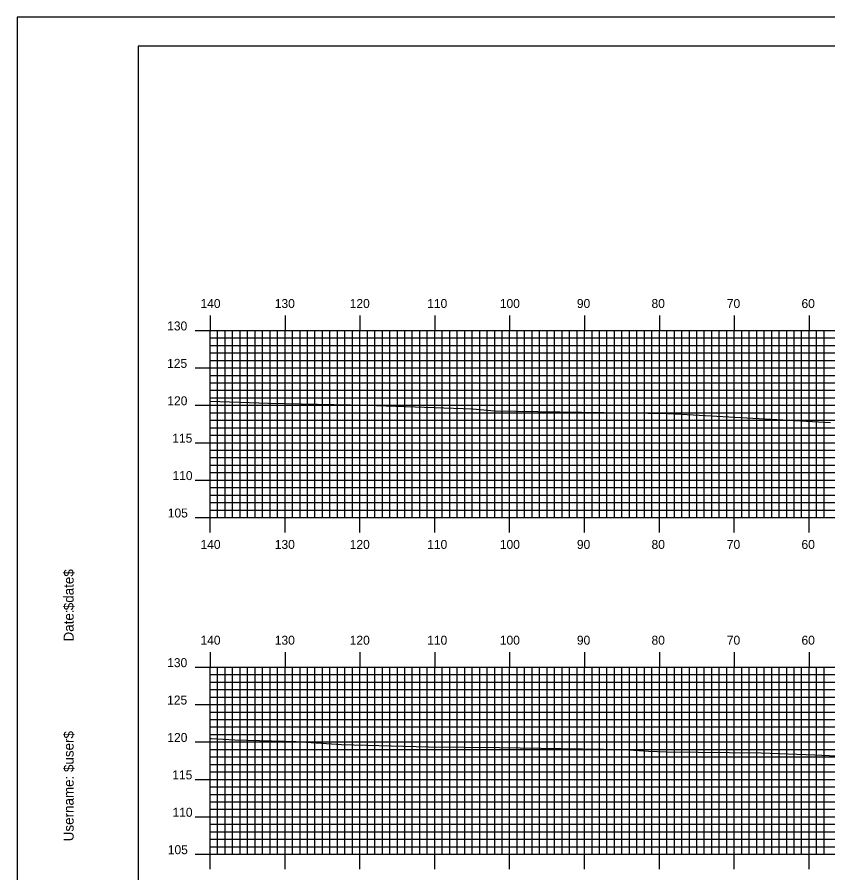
# Model space of a CAD drawing. Extents: x 1772022 to 1772366, y 442591 to 442811.
# Drawn here: x 1772022.3 to 1772130.6, y 442696.2 to 442810.5 of the extents above; entities that cross this region are included whole.
import ezdxf

# ---------------------------------------------------------------- set-up
doc = ezdxf.new("R2010")
doc.units = 0
for name, color, linetype in [('BORDER', 7, 'Continuous'), ('H_V ANNOTATION', 7, 'Continuous'), ('MAJOR', 7, 'Continuous'), ('MINOR', 7, 'Continuous'), ('PLOT BOUNDARY', 7, 'Continuous'), ('S_Roadway_Centerline', 7, 'Continuous')]:
    doc.layers.add(name, color=color, linetype=linetype)

msp = doc.modelspace()

# ---------------------------------------------------------------- linework, layer by layer
at = {"layer": 'BORDER'}
msp.add_lwpolyline([(1772038.49, 442596.67), (1772358.49, 442596.67), (1772358.49, 442806.67), (1772038.49, 442806.67)], close=True, dxfattribs=at)
at = {"layer": 'MAJOR'}
for p, q in [((1772048.09, 442770.67), (1772048.09, 442768.67)), ((1772058.09, 442770.67), (1772058.09, 442768.67)), ((1772068.09, 442770.67), (1772068.09, 442768.67)), ((1772078.09, 442770.67), (1772078.09, 442768.67)), ((1772088.09, 442770.67), (1772088.09, 442768.67)), ((1772098.09, 442770.67), (1772098.09, 442768.67)), ((1772108.09, 442770.67), (1772108.09, 442768.67)), ((1772118.09, 442770.67), (1772118.09, 442768.67)), ((1772128.09, 442770.67), (1772128.09, 442768.67)), ((1772046.09, 442768.67), (1772048.09, 442768.67)), ((1772048.09, 442768.67), (1772328.09, 442768.67)), ((1772048.09, 442743.67), (1772048.09, 442768.67)), ((1772048.09, 442743.67), (1772048.09, 442768.67)), ((1772048.09, 442768.67), (1772328.09, 442768.67)), ((1772058.09, 442743.67), (1772058.09, 442768.67)), ((1772068.09, 442743.67), (1772068.09, 442768.67)), ((1772078.09, 442743.67), (1772078.09, 442768.67)), ((1772088.09, 442743.67), (1772088.09, 442768.67)), ((1772098.09, 442743.67), (1772098.09, 442768.67)), ((1772108.09, 442743.67), (1772108.09, 442768.67)), ((1772118.09, 442743.67), (1772118.09, 442768.67)), ((1772128.09, 442743.67), (1772128.09, 442768.67)), ((1772046.09, 442763.67), (1772048.09, 442763.67)), ((1772048.09, 442763.67), (1772328.09, 442763.67)), ((1772046.09, 442758.67), (1772048.09, 442758.67)), ((1772048.09, 442758.67), (1772328.09, 442758.67)), ((1772046.09, 442753.67), (1772048.09, 442753.67)), ((1772048.09, 442753.67), (1772328.09, 442753.67)), ((1772046.09, 442748.67), (1772048.09, 442748.67)), ((1772048.09, 442748.67), (1772328.09, 442748.67)), ((1772046.09, 442743.67), (1772048.09, 442743.67)), ((1772048.09, 442743.67), (1772328.09, 442743.67)), ((1772048.09, 442743.67), (1772328.09, 442743.67)), ((1772048.09, 442741.66), (1772048.09, 442743.67)), ((1772058.09, 442741.66), (1772058.09, 442743.67)), ((1772068.09, 442741.66), (1772068.09, 442743.67)), ((1772078.09, 442741.66), (1772078.09, 442743.67)), ((1772088.09, 442741.66), (1772088.09, 442743.67)), ((1772098.09, 442741.66), (1772098.09, 442743.67)), ((1772108.09, 442741.66), (1772108.09, 442743.67)), ((1772118.09, 442741.66), (1772118.09, 442743.67)), ((1772128.09, 442741.66), (1772128.09, 442743.67)), ((1772048.09, 442725.67), (1772048.09, 442723.67)), ((1772058.09, 442725.67), (1772058.09, 442723.67)), ((1772068.09, 442725.67), (1772068.09, 442723.67)), ((1772078.09, 442725.67), (1772078.09, 442723.67)), ((1772088.09, 442725.67), (1772088.09, 442723.67)), ((1772098.09, 442725.67), (1772098.09, 442723.67)), ((1772108.09, 442725.67), (1772108.09, 442723.67)), ((1772118.09, 442725.67), (1772118.09, 442723.67)), ((1772128.09, 442725.67), (1772128.09, 442723.67)), ((1772046.09, 442723.67), (1772048.09, 442723.67)), ((1772048.09, 442698.67), (1772048.09, 442723.67)), ((1772048.09, 442698.67), (1772048.09, 442723.67)), ((1772048.09, 442723.67), (1772328.09, 442723.67)), ((1772048.09, 442723.67), (1772328.09, 442723.67)), ((1772058.09, 442698.67), (1772058.09, 442723.67)), ((1772068.09, 442698.67), (1772068.09, 442723.67)), ((1772078.09, 442698.67), (1772078.09, 442723.67)), ((1772088.09, 442698.67), (1772088.09, 442723.67)), ((1772098.09, 442698.67), (1772098.09, 442723.67)), ((1772108.09, 442698.67), (1772108.09, 442723.67)), ((1772118.09, 442698.67), (1772118.09, 442723.67)), ((1772128.09, 442698.67), (1772128.09, 442723.67)), ((1772046.09, 442718.67), (1772048.09, 442718.67)), ((1772048.09, 442718.67), (1772328.09, 442718.67)), ((1772046.09, 442713.67), (1772048.09, 442713.67)), ((1772048.09, 442713.67), (1772328.09, 442713.67)), ((1772046.09, 442708.67), (1772048.09, 442708.67)), ((1772048.09, 442708.67), (1772328.09, 442708.67)), ((1772046.09, 442703.67), (1772048.09, 442703.67)), ((1772048.09, 442703.67), (1772328.09, 442703.67)), ((1772046.09, 442698.67), (1772048.09, 442698.67)), ((1772048.09, 442696.66), (1772048.09, 442698.67)), ((1772048.09, 442698.67), (1772328.09, 442698.67)), ((1772048.09, 442698.67), (1772328.09, 442698.67)), ((1772058.09, 442696.66), (1772058.09, 442698.67)), ((1772068.09, 442696.66), (1772068.09, 442698.67)), ((1772078.09, 442696.66), (1772078.09, 442698.67)), ((1772088.09, 442696.66), (1772088.09, 442698.67)), ((1772098.09, 442696.66), (1772098.09, 442698.67)), ((1772108.09, 442696.66), (1772108.09, 442698.67)), ((1772118.09, 442696.66), (1772118.09, 442698.67)), ((1772128.09, 442696.66), (1772128.09, 442698.67))]:
    msp.add_line(p, q, dxfattribs=at)
at = {"layer": 'MINOR'}
for p, q in [((1772048.09, 442767.67), (1772328.09, 442767.67)), ((1772048.09, 442767.67), (1772050.1, 442767.67)), ((1772049.09, 442743.67), (1772049.09, 442768.67)), ((1772050.09, 442743.67), (1772050.09, 442768.67)), ((1772051.09, 442743.67), (1772051.09, 442768.67)), ((1772052.09, 442743.67), (1772052.09, 442768.67)), ((1772053.09, 442743.67), (1772053.09, 442768.67)), ((1772054.09, 442743.67), (1772054.09, 442768.67)), ((1772055.09, 442743.67), (1772055.09, 442768.67)), ((1772056.09, 442743.67), (1772056.09, 442768.67)), ((1772057.09, 442743.67), (1772057.09, 442768.67)), ((1772059.09, 442743.67), (1772059.09, 442768.67)), ((1772060.09, 442743.67), (1772060.09, 442768.67)), ((1772061.09, 442743.67), (1772061.09, 442768.67)), ((1772062.09, 442743.67), (1772062.09, 442768.67)), ((1772063.09, 442743.67), (1772063.09, 442768.67)), ((1772064.09, 442743.67), (1772064.09, 442768.67)), ((1772065.09, 442743.67), (1772065.09, 442768.67)), ((1772066.09, 442743.67), (1772066.09, 442768.67)), ((1772067.09, 442743.67), (1772067.09, 442768.67)), ((1772069.09, 442743.67), (1772069.09, 442768.67)), ((1772070.09, 442743.67), (1772070.09, 442768.67)), ((1772071.09, 442743.67), (1772071.09, 442768.67)), ((1772072.09, 442743.67), (1772072.09, 442768.67)), ((1772073.09, 442743.67), (1772073.09, 442768.67)), ((1772074.09, 442743.67), (1772074.09, 442768.67)), ((1772075.09, 442743.67), (1772075.09, 442768.67)), ((1772076.09, 442743.67), (1772076.09, 442768.67)), ((1772077.09, 442743.67), (1772077.09, 442768.67)), ((1772079.09, 442743.67), (1772079.09, 442768.67)), ((1772080.09, 442743.67), (1772080.09, 442768.67)), ((1772081.09, 442743.67), (1772081.09, 442768.67)), ((1772082.09, 442743.67), (1772082.09, 442768.67)), ((1772083.09, 442743.67), (1772083.09, 442768.67)), ((1772084.09, 442743.67), (1772084.09, 442768.67)), ((1772085.09, 442743.67), (1772085.09, 442768.67)), ((1772086.09, 442743.67), (1772086.09, 442768.67)), ((1772087.09, 442743.67), (1772087.09, 442768.67)), ((1772089.09, 442743.67), (1772089.09, 442768.67)), ((1772090.09, 442743.67), (1772090.09, 442768.67)), ((1772091.09, 442743.67), (1772091.09, 442768.67)), ((1772092.09, 442743.67), (1772092.09, 442768.67)), ((1772093.09, 442743.67), (1772093.09, 442768.67)), ((1772094.09, 442743.67), (1772094.09, 442768.67)), ((1772095.09, 442743.67), (1772095.09, 442768.67)), ((1772096.09, 442743.67), (1772096.09, 442768.67)), ((1772097.09, 442743.67), (1772097.09, 442768.67)), ((1772099.09, 442743.67), (1772099.09, 442768.67)), ((1772100.09, 442743.67), (1772100.09, 442768.67)), ((1772101.09, 442743.67), (1772101.09, 442768.67)), ((1772102.09, 442743.67), (1772102.09, 442768.67)), ((1772103.09, 442743.67), (1772103.09, 442768.67)), ((1772104.09, 442743.67), (1772104.09, 442768.67)), ((1772105.09, 442743.67), (1772105.09, 442768.67)), ((1772106.09, 442743.67), (1772106.09, 442768.67)), ((1772107.09, 442743.67), (1772107.09, 442768.67)), ((1772109.09, 442743.67), (1772109.09, 442768.67)), ((1772110.09, 442743.67), (1772110.09, 442768.67)), ((1772111.09, 442743.67), (1772111.09, 442768.67)), ((1772112.09, 442743.67), (1772112.09, 442768.67)), ((1772113.09, 442743.67), (1772113.09, 442768.67)), ((1772114.09, 442743.67), (1772114.09, 442768.67)), ((1772115.09, 442743.67), (1772115.09, 442768.67)), ((1772116.09, 442743.67), (1772116.09, 442768.67)), ((1772117.09, 442743.67), (1772117.09, 442768.67)), ((1772119.09, 442743.67), (1772119.09, 442768.67)), ((1772120.09, 442743.67), (1772120.09, 442768.67)), ((1772121.09, 442743.67), (1772121.09, 442768.67)), ((1772122.09, 442743.67), (1772122.09, 442768.67)), ((1772123.09, 442743.67), (1772123.09, 442768.67)), ((1772124.09, 442743.67), (1772124.09, 442768.67)), ((1772125.09, 442743.67), (1772125.09, 442768.67)), ((1772126.09, 442743.67), (1772126.09, 442768.67)), ((1772127.09, 442743.67), (1772127.09, 442768.67)), ((1772129.09, 442743.67), (1772129.09, 442768.67)), ((1772130.09, 442743.67), (1772130.09, 442768.67)), ((1772048.09, 442766.67), (1772328.09, 442766.67)), ((1772048.09, 442766.67), (1772050.1, 442766.67)), ((1772048.09, 442765.67), (1772328.09, 442765.67)), ((1772048.09, 442765.67), (1772050.1, 442765.67)), ((1772048.09, 442764.67), (1772328.09, 442764.67)), ((1772048.09, 442764.67), (1772050.1, 442764.67)), ((1772048.09, 442762.67), (1772328.09, 442762.67)), ((1772048.09, 442762.67), (1772050.1, 442762.67)), ((1772048.09, 442761.67), (1772328.09, 442761.67)), ((1772048.09, 442761.67), (1772050.1, 442761.67)), ((1772048.09, 442760.67), (1772328.09, 442760.67)), ((1772048.09, 442760.67), (1772050.1, 442760.67)), ((1772048.09, 442759.67), (1772328.09, 442759.67)), ((1772048.09, 442759.67), (1772050.1, 442759.67)), ((1772048.09, 442757.67), (1772328.09, 442757.67)), ((1772048.09, 442757.67), (1772050.1, 442757.67)), ((1772048.09, 442756.67), (1772328.09, 442756.67)), ((1772048.09, 442756.67), (1772050.1, 442756.67)), ((1772048.09, 442755.67), (1772328.09, 442755.67)), ((1772048.09, 442755.67), (1772050.1, 442755.67)), ((1772048.09, 442754.67), (1772328.09, 442754.67)), ((1772048.09, 442754.67), (1772050.1, 442754.67)), ((1772048.09, 442752.67), (1772328.09, 442752.67)), ((1772048.09, 442752.67), (1772050.1, 442752.67)), ((1772048.09, 442751.67), (1772328.09, 442751.67)), ((1772048.09, 442751.67), (1772050.1, 442751.67)), ((1772048.09, 442750.67), (1772328.09, 442750.67)), ((1772048.09, 442750.67), (1772050.1, 442750.67)), ((1772048.09, 442749.67), (1772328.09, 442749.67)), ((1772048.09, 442749.67), (1772050.1, 442749.67)), ((1772048.09, 442747.67), (1772328.09, 442747.67)), ((1772048.09, 442747.67), (1772050.1, 442747.67)), ((1772048.09, 442746.67), (1772328.09, 442746.67)), ((1772048.09, 442746.67), (1772050.1, 442746.67)), ((1772048.09, 442745.67), (1772328.09, 442745.67)), ((1772048.09, 442745.67), (1772050.1, 442745.67)), ((1772048.09, 442744.67), (1772328.09, 442744.67)), ((1772048.09, 442744.67), (1772050.1, 442744.67)), ((1772048.09, 442698.67), (1772048.09, 442723.67)), ((1772049.09, 442698.67), (1772049.09, 442723.67)), ((1772050.09, 442698.67), (1772050.09, 442723.67)), ((1772051.09, 442698.67), (1772051.09, 442723.67)), ((1772052.09, 442698.67), (1772052.09, 442723.67)), ((1772053.09, 442698.67), (1772053.09, 442723.67)), ((1772054.09, 442698.67), (1772054.09, 442723.67)), ((1772055.09, 442698.67), (1772055.09, 442723.67)), ((1772056.09, 442698.67), (1772056.09, 442723.67)), ((1772057.09, 442698.67), (1772057.09, 442723.67)), ((1772059.09, 442698.67), (1772059.09, 442723.67)), ((1772060.09, 442698.67), (1772060.09, 442723.67)), ((1772061.09, 442698.67), (1772061.09, 442723.67)), ((1772062.09, 442698.67), (1772062.09, 442723.67)), ((1772063.09, 442698.67), (1772063.09, 442723.67)), ((1772064.09, 442698.67), (1772064.09, 442723.67)), ((1772065.09, 442698.67), (1772065.09, 442723.67)), ((1772066.09, 442698.67), (1772066.09, 442723.67)), ((1772067.09, 442698.67), (1772067.09, 442723.67)), ((1772069.09, 442698.67), (1772069.09, 442723.67)), ((1772070.09, 442698.67), (1772070.09, 442723.67)), ((1772071.09, 442698.67), (1772071.09, 442723.67)), ((1772072.09, 442698.67), (1772072.09, 442723.67)), ((1772073.09, 442698.67), (1772073.09, 442723.67)), ((1772074.09, 442698.67), (1772074.09, 442723.67)), ((1772075.09, 442698.67), (1772075.09, 442723.67)), ((1772076.09, 442698.67), (1772076.09, 442723.67)), ((1772077.09, 442698.67), (1772077.09, 442723.67)), ((1772079.09, 442698.67), (1772079.09, 442723.67)), ((1772080.09, 442698.67), (1772080.09, 442723.67)), ((1772081.09, 442698.67), (1772081.09, 442723.67)), ((1772082.09, 442698.67), (1772082.09, 442723.67)), ((1772083.09, 442698.67), (1772083.09, 442723.67)), ((1772084.09, 442698.67), (1772084.09, 442723.67)), ((1772085.09, 442698.67), (1772085.09, 442723.67)), ((1772086.09, 442698.67), (1772086.09, 442723.67)), ((1772087.09, 442698.67), (1772087.09, 442723.67)), ((1772089.09, 442698.67), (1772089.09, 442723.67)), ((1772090.09, 442698.67), (1772090.09, 442723.67)), ((1772091.09, 442698.67), (1772091.09, 442723.67)), ((1772092.09, 442698.67), (1772092.09, 442723.67)), ((1772093.09, 442698.67), (1772093.09, 442723.67)), ((1772094.09, 442698.67), (1772094.09, 442723.67)), ((1772095.09, 442698.67), (1772095.09, 442723.67)), ((1772096.09, 442698.67), (1772096.09, 442723.67)), ((1772097.09, 442698.67), (1772097.09, 442723.67)), ((1772099.09, 442698.67), (1772099.09, 442723.67)), ((1772100.09, 442698.67), (1772100.09, 442723.67)), ((1772101.09, 442698.67), (1772101.09, 442723.67)), ((1772102.09, 442698.67), (1772102.09, 442723.67)), ((1772103.09, 442698.67), (1772103.09, 442723.67)), ((1772104.09, 442698.67), (1772104.09, 442723.67)), ((1772105.09, 442698.67), (1772105.09, 442723.67)), ((1772106.09, 442698.67), (1772106.09, 442723.67)), ((1772107.09, 442698.67), (1772107.09, 442723.67)), ((1772109.09, 442698.67), (1772109.09, 442723.67)), ((1772110.09, 442698.67), (1772110.09, 442723.67)), ((1772111.09, 442698.67), (1772111.09, 442723.67)), ((1772112.09, 442698.67), (1772112.09, 442723.67)), ((1772113.09, 442698.67), (1772113.09, 442723.67)), ((1772114.09, 442698.67), (1772114.09, 442723.67)), ((1772115.09, 442698.67), (1772115.09, 442723.67)), ((1772116.09, 442698.67), (1772116.09, 442723.67)), ((1772117.09, 442698.67), (1772117.09, 442723.67)), ((1772119.09, 442698.67), (1772119.09, 442723.67)), ((1772120.09, 442698.67), (1772120.09, 442723.67)), ((1772121.09, 442698.67), (1772121.09, 442723.67)), ((1772122.09, 442698.67), (1772122.09, 442723.67)), ((1772123.09, 442698.67), (1772123.09, 442723.67)), ((1772124.09, 442698.67), (1772124.09, 442723.67)), ((1772125.09, 442698.67), (1772125.09, 442723.67)), ((1772126.09, 442698.67), (1772126.09, 442723.67)), ((1772127.09, 442698.67), (1772127.09, 442723.67)), ((1772129.09, 442698.67), (1772129.09, 442723.67)), ((1772130.09, 442698.67), (1772130.09, 442723.67)), ((1772048.09, 442722.67), (1772050.1, 442722.67)), ((1772048.09, 442722.67), (1772328.09, 442722.67)), ((1772048.09, 442721.67), (1772050.1, 442721.67)), ((1772048.09, 442721.67), (1772328.09, 442721.67)), ((1772048.09, 442720.67), (1772050.1, 442720.67)), ((1772048.09, 442720.67), (1772328.09, 442720.67)), ((1772048.09, 442719.67), (1772050.1, 442719.67)), ((1772048.09, 442719.67), (1772328.09, 442719.67)), ((1772048.09, 442717.67), (1772050.1, 442717.67)), ((1772048.09, 442717.67), (1772328.09, 442717.67)), ((1772048.09, 442716.67), (1772050.1, 442716.67)), ((1772048.09, 442716.67), (1772328.09, 442716.67)), ((1772048.09, 442715.67), (1772050.1, 442715.67)), ((1772048.09, 442715.67), (1772328.09, 442715.67)), ((1772048.09, 442714.67), (1772050.1, 442714.67)), ((1772048.09, 442714.67), (1772328.09, 442714.67)), ((1772048.09, 442712.67), (1772050.1, 442712.67)), ((1772048.09, 442712.67), (1772328.09, 442712.67)), ((1772048.09, 442711.67), (1772050.1, 442711.67)), ((1772048.09, 442711.67), (1772328.09, 442711.67)), ((1772048.09, 442710.67), (1772050.1, 442710.67)), ((1772048.09, 442710.67), (1772328.09, 442710.67)), ((1772048.09, 442709.67), (1772050.1, 442709.67)), ((1772048.09, 442709.67), (1772328.09, 442709.67)), ((1772048.09, 442707.67), (1772050.1, 442707.67)), ((1772048.09, 442707.67), (1772328.09, 442707.67)), ((1772048.09, 442706.67), (1772050.1, 442706.67)), ((1772048.09, 442706.67), (1772328.09, 442706.67)), ((1772048.09, 442705.67), (1772050.1, 442705.67)), ((1772048.09, 442705.67), (1772328.09, 442705.67)), ((1772048.09, 442704.67), (1772050.1, 442704.67)), ((1772048.09, 442704.67), (1772328.09, 442704.67)), ((1772048.09, 442702.67), (1772050.1, 442702.67)), ((1772048.09, 442702.67), (1772328.09, 442702.67)), ((1772048.09, 442701.67), (1772050.1, 442701.67)), ((1772048.09, 442701.67), (1772328.09, 442701.67)), ((1772048.09, 442700.67), (1772050.1, 442700.67)), ((1772048.09, 442700.67), (1772328.09, 442700.67)), ((1772048.09, 442699.67), (1772050.1, 442699.67)), ((1772048.09, 442699.67), (1772328.09, 442699.67))]:
    msp.add_line(p, q, dxfattribs=at)
at = {"layer": 'PLOT BOUNDARY'}
msp.add_lwpolyline([(1772022.31, 442590.55), (1772362.31, 442590.55), (1772362.31, 442810.55), (1772022.31, 442810.55)], close=True, dxfattribs=at)
at = {"layer": 'S_Roadway_Centerline'}
for points in [[(1772048.09, 442759.21), (1772055.88, 442758.93), (1772069.01, 442758.68), (1772083.17, 442758.19), (1772086.06, 442757.91), (1772088.92, 442757.86), (1772106.55, 442757.61), (1772109.24, 442757.56), (1772109.62, 442757.56), (1772110.18, 442757.52), (1772130.93, 442756.35)], [(1772048.09, 442714.14), (1772048.25, 442714.13), (1772051.4, 442713.95), (1772059.59, 442713.74), (1772065.65, 442713.31), (1772077.26, 442713.03), (1772086.72, 442712.95), (1772103.37, 442712.67), (1772106.62, 442712.46), (1772109.02, 442712.35), (1772121.69, 442712.2), (1772128.85, 442711.96), (1772131.71, 442711.83)]]:
    msp.add_lwpolyline(points, dxfattribs=at)

# ---------------------------------------------------------------- texts
at = {"layer": 'BORDER'}
for s, p in [('$date$', (1772029.86, 442731.28)), ('Date:', (1772029.86, 442727.1)), ('$user$', (1772029.86, 442709.65)), ('Username:', (1772029.86, 442700.4))]:
    msp.add_text(s, height=1.339, rotation=90, dxfattribs=at).set_placement(p)
at = {"layer": 'H_V ANNOTATION'}
for s, p in [('140', (1772046.8, 442771.67)), ('130', (1772056.72, 442771.67)), ('120', (1772066.73, 442771.67)), ('110', (1772077.08, 442771.67)), ('100', (1772086.78, 442771.67)), ('90', (1772097.07, 442771.67)), ('80', (1772107.04, 442771.67)), ('70', (1772117.1, 442771.67)), ('60', (1772127.07, 442771.67)), ('130', (1772042.35, 442768.67)), ('125', (1772042.34, 442763.67)), ('120', (1772042.37, 442758.67)), ('115', (1772043.03, 442753.67)), ('110', (1772043.06, 442748.67)), ('105', (1772042.43, 442743.67)), ('140', (1772046.8, 442739.47)), ('130', (1772056.72, 442739.47)), ('120', (1772066.73, 442739.47)), ('110', (1772077.08, 442739.47)), ('100', (1772086.78, 442739.47)), ('90', (1772097.07, 442739.47)), ('80', (1772107.04, 442739.47)), ('70', (1772117.1, 442739.47)), ('60', (1772127.07, 442739.47)), ('140', (1772046.8, 442726.67)), ('130', (1772056.72, 442726.67)), ('120', (1772066.73, 442726.67)), ('110', (1772077.08, 442726.67)), ('100', (1772086.78, 442726.67)), ('90', (1772097.07, 442726.67)), ('80', (1772107.04, 442726.67)), ('70', (1772117.1, 442726.67)), ('60', (1772127.07, 442726.67)), ('130', (1772042.35, 442723.67)), ('125', (1772042.34, 442718.67)), ('120', (1772042.37, 442713.67)), ('115', (1772043.03, 442708.67)), ('110', (1772043.06, 442703.67)), ('105', (1772042.43, 442698.67))]:
    msp.add_text(s, height=1.2, dxfattribs=at).set_placement(p)
at = {"layer": 'MAJOR'}
for p in [(1772048.08, 442743.67), (1772048.08, 442698.67)]:
    msp.add_text('-', height=0.012, dxfattribs=at).set_placement(p)

doc.saveas('drawing.dxf')
